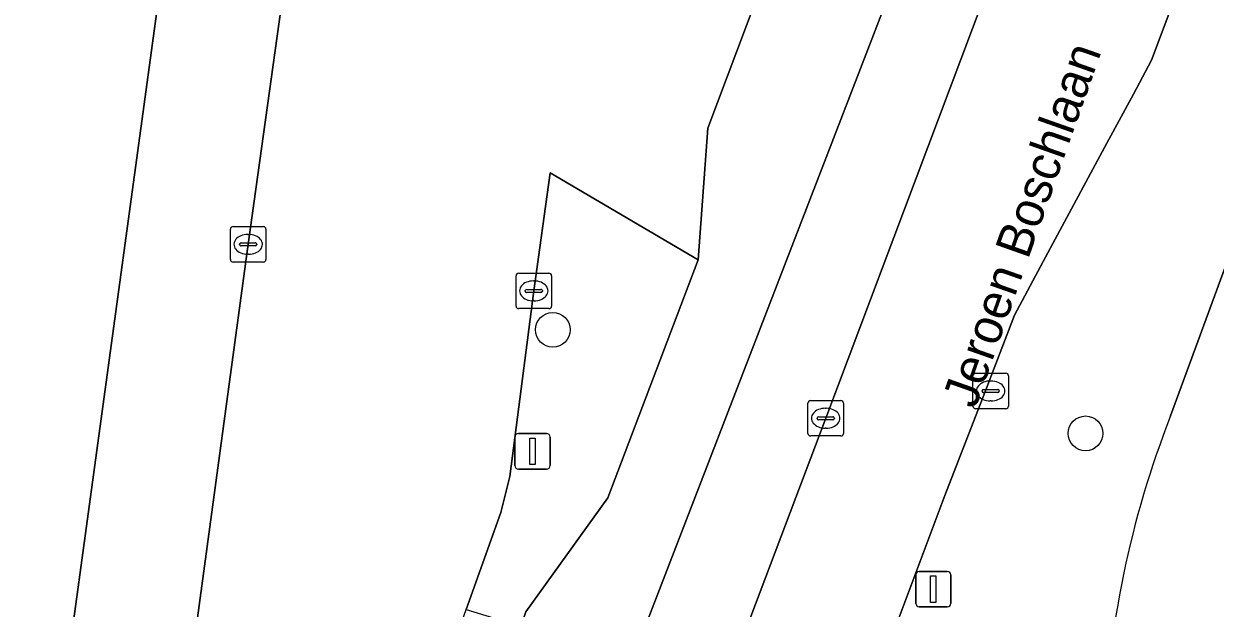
# Model space of a CAD drawing. Extents: x 162172 to 163187, y 382874 to 383685.
# Drawn here: x 163098.41 to 163131.97, y 383004.01 to 383020.47 of the extents above; entities that cross this region are included whole.
import ezdxf

# ---------------------------------------------------------------- set-up
doc = ezdxf.new("R2010")
doc.units = 0
for name, color, linetype in [('IMGEO_Berm_groen', 7, 'Continuous'), ('IMGEO_Boom', 7, 'Continuous'), ('IMGEO_Erf', 7, 'Continuous'), ('IMGEO_Fietspad_gesloten', 7, 'Continuous'), ('IMGEO_Kolk', 7, 'Continuous'), ('IMGEO_Lichtmast', 7, 'Continuous'), ('IMGEO_Openbare_ruimte_label', 7, 'Continuous'), ('IMGEO_Parkeervlak_open', 7, 'Continuous'), ('IMGEO_Rijbaan_lokaal_gesloten', 7, 'Continuous'), ('IMGEO_Voetpad_open', 7, 'Continuous')]:
    doc.layers.add(name, color=color, linetype=linetype)

msp = doc.modelspace()

# ---------------------------------------------------------------- linework, layer by layer
at = {"layer": 'IMGEO_Berm_groen'}
for points in [[(163142.501, 383044.918), (163137.777, 383032.423), (163135.415, 383033.359), (163134.125, 383029.959), (163130.174, 383019.451), (163129.662, 383018.485), (163128.915, 383017.105), (163127.523, 383014.531), (163127.123, 383013.779), (163126.316, 383012.264), (163125.474, 383010.089), (163124.351, 383007.183), (163121.897, 383000.656), (163120.735, 382997.497), (163120.127, 382995.283), (163117.88, 382989.013)], [(163130.709, 383009.426), (163138.112, 383029.587)], [(163138.112, 383029.587), (163130.709, 383009.426)]]:
    msp.add_lwpolyline(points, dxfattribs=at)
msp.add_lwpolyline([(163117.406, 383013.827), (163113.236, 383016.27), (163112.775, 383012.95), (163112.099, 383007.718), (163111.846, 383006.708), (163110.871, 383003.977), (163112.409, 383003.508), (163112.554, 383003.909), (163114.863, 383007.118)], close=True, dxfattribs=at)
msp.add_arc((163156.244, 382999.418), 27.426, 158.5987, 178.0992, dxfattribs=at)
msp.add_arc((163156.244, 382999.418), 27.426, 158.5987, 178.0992, dxfattribs=at)
at = {"layer": 'IMGEO_Boom'}
for centre in [(163113.311, 383011.854), (163128.316, 383008.936)]:
    msp.add_circle(centre, 0.489, dxfattribs=at)
at = {"layer": 'IMGEO_Erf'}
msp.add_lwpolyline([(163098.172, 383039.026), (163098.631, 383038.933), (163096.551, 383029.516), (163093.637, 383030.155), (163092.186, 383030.473), (163088.911, 383015.365), (163090.381, 383015.036), (163095.779, 383013.826), (163092.68, 383000), (163090.912, 382992.113), (163093.008, 382991.643), (163092.948, 382991.201), (163097.992, 382990.342), (163099.312, 383000), (163102.12, 383020.545), (163105.322, 383043.799)], dxfattribs=at)
at = {"layer": 'IMGEO_Fietspad_gesloten'}
for points in [[(163126.175, 383040.302), (163125.052, 383037.224), (163120.155, 383024.119), (163117.673, 383017.534), (163117.406, 383013.827), (163114.863, 383007.118), (163112.554, 383003.909), (163112.409, 383003.508), (163111.139, 383000), (163108.118, 382991.652), (163106.398, 382986.646)], [(163115.606, 383002.688), (163123.356, 383022.795)]]:
    msp.add_lwpolyline(points, dxfattribs=at)
at = {"layer": 'IMGEO_Kolk'}
for p, q in [((163104.232, 383013.834), (163104.232, 383014.686)), ((163104.307, 383014.76), (163105.159, 383014.76)), ((163105.233, 383014.686), (163105.233, 383013.834)), ((163104.72, 383014.54), (163104.745, 383014.54)), ((163104.491, 383014.254), (163104.491, 383014.266)), ((163104.929, 383014.217), (163104.531, 383014.217)), ((163104.534, 383014.303), (163104.932, 383014.303)), ((163104.743, 383013.98), (163104.718, 383013.98)), ((163104.975, 383014.266), (163104.975, 383014.254)), ((163105.159, 383013.76), (163104.307, 383013.76)), ((163112.275, 383012.523), (163112.275, 383013.375)), ((163112.35, 383013.449), (163113.202, 383013.449)), ((163113.276, 383013.375), (163113.276, 383012.523)), ((163112.577, 383012.992), (163112.975, 383012.992)), ((163112.763, 383013.229), (163112.788, 383013.229)), ((163112.534, 383012.943), (163112.534, 383012.955)), ((163112.972, 383012.906), (163112.574, 383012.906)), ((163112.786, 383012.669), (163112.761, 383012.669)), ((163113.018, 383012.955), (163113.018, 383012.943)), ((163113.202, 383012.449), (163112.35, 383012.449)), ((163125.218, 383010.631), (163126.07, 383010.631)), ((163125.143, 383009.705), (163125.143, 383010.557)), ((163125.631, 383010.411), (163125.656, 383010.411)), ((163126.144, 383010.557), (163126.144, 383009.705)), ((163125.402, 383010.125), (163125.402, 383010.137)), ((163125.84, 383010.088), (163125.442, 383010.088)), ((163125.445, 383010.174), (163125.843, 383010.174)), ((163125.886, 383010.137), (163125.886, 383010.125)), ((163120.497, 383008.936), (163120.497, 383009.788)), ((163120.572, 383009.862), (163121.424, 383009.862)), ((163120.985, 383009.642), (163121.01, 383009.642)), ((163121.498, 383009.788), (163121.498, 383008.936)), ((163126.07, 383009.631), (163125.218, 383009.631)), ((163125.654, 383009.851), (163125.629, 383009.851)), ((163120.756, 383009.356), (163120.756, 383009.368)), ((163121.194, 383009.319), (163120.796, 383009.319)), ((163120.799, 383009.405), (163121.197, 383009.405)), ((163121.24, 383009.368), (163121.24, 383009.356)), ((163121.008, 383009.082), (163120.983, 383009.082)), ((163121.424, 383008.862), (163120.572, 383008.862))]:
    msp.add_line(p, q, dxfattribs=at)
for points in [[(163104.232, 383013.834), (163104.232, 383014.686)], [(163104.307, 383014.76), (163105.159, 383014.76)], [(163105.233, 383014.686), (163105.233, 383013.834)], [(163105.159, 383013.76), (163104.307, 383013.76)], [(163112.275, 383012.523), (163112.275, 383013.375)], [(163112.35, 383013.449), (163113.202, 383013.449)], [(163113.276, 383013.375), (163113.276, 383012.523)], [(163113.202, 383012.449), (163112.35, 383012.449)], [(163125.218, 383010.631), (163126.07, 383010.631)], [(163125.143, 383009.705), (163125.143, 383010.557)], [(163126.144, 383010.557), (163126.144, 383009.705)], [(163120.497, 383008.936), (163120.497, 383009.788)], [(163120.572, 383009.862), (163121.424, 383009.862)], [(163121.498, 383009.788), (163121.498, 383008.936)], [(163126.07, 383009.631), (163125.218, 383009.631)], [(163121.424, 383008.862), (163120.572, 383008.862)]]:
    msp.add_lwpolyline(points, dxfattribs=at)
for centre, radius, start, end in [((163104.309, 383014.684), 0.0765, 91.552, 178.448), ((163104.309, 383014.684), 0.0765, 91.552, 178.448), ((163105.157, 383014.684), 0.0765, 1.552, 88.448), ((163105.157, 383014.684), 0.0765, 1.552, 88.448), ((163104.531, 383014.263), 0.0403, 85.8775, 175.7526), ((163104.528, 383014.253), 0.0366, 178.938, 274.7102), ((163104.932, 383014.26), 0.043, 264.8664, 352.4533), ((163104.936, 383014.265), 0.0386, 1.7309, 96.639), ((163104.309, 383013.836), 0.0765, 181.552, 268.448), ((163104.309, 383013.836), 0.0765, 181.552, 268.448), ((163105.157, 383013.836), 0.0765, 271.552, 358.448), ((163105.157, 383013.836), 0.0765, 271.552, 358.448), ((163112.352, 383013.373), 0.0765, 91.552, 178.448), ((163112.352, 383013.373), 0.0765, 91.552, 178.448), ((163113.2, 383013.373), 0.0765, 1.552, 88.448), ((163113.2, 383013.373), 0.0765, 1.552, 88.448), ((163112.574, 383012.952), 0.0403, 85.8775, 175.7526), ((163112.979, 383012.954), 0.0386, 1.7309, 96.639), ((163112.571, 383012.942), 0.0366, 178.938, 274.7102), ((163112.975, 383012.949), 0.043, 264.8664, 352.4533), ((163112.352, 383012.525), 0.0765, 181.552, 268.448), ((163112.352, 383012.525), 0.0765, 181.552, 268.448), ((163113.2, 383012.525), 0.0765, 271.552, 358.448), ((163113.2, 383012.525), 0.0765, 271.552, 358.448), ((163125.22, 383010.555), 0.0765, 91.552, 178.448), ((163125.22, 383010.555), 0.0765, 91.552, 178.448), ((163126.068, 383010.555), 0.0765, 1.552, 88.448), ((163126.068, 383010.555), 0.0765, 1.552, 88.448), ((163125.442, 383010.134), 0.0403, 85.8775, 175.7526), ((163125.439, 383010.124), 0.0366, 178.938, 274.7102), ((163125.843, 383010.131), 0.043, 264.8664, 352.4533), ((163125.847, 383010.136), 0.0386, 1.7309, 96.639), ((163120.574, 383009.786), 0.0765, 91.552, 178.448), ((163120.574, 383009.786), 0.0765, 91.552, 178.448), ((163121.422, 383009.786), 0.0765, 1.552, 88.448), ((163121.422, 383009.786), 0.0765, 1.552, 88.448), ((163125.22, 383009.707), 0.0765, 181.552, 268.448), ((163125.22, 383009.707), 0.0765, 181.552, 268.448), ((163126.068, 383009.707), 0.0765, 271.552, 358.448), ((163126.068, 383009.707), 0.0765, 271.552, 358.448), ((163120.796, 383009.365), 0.0403, 85.8775, 175.7526), ((163120.793, 383009.355), 0.0366, 178.938, 274.7102), ((163121.197, 383009.362), 0.043, 264.8664, 352.4533), ((163121.201, 383009.367), 0.0386, 1.7309, 96.639), ((163120.574, 383008.938), 0.0765, 181.552, 268.448), ((163120.574, 383008.938), 0.0765, 181.552, 268.448), ((163121.422, 383008.938), 0.0765, 271.552, 358.448), ((163121.422, 383008.938), 0.0765, 271.552, 358.448)]:
    msp.add_arc(centre, radius, start, end, dxfattribs=at)
for centre, major_axis, ratio, start_param, end_param in [((163104.719, 383014.26), (-0.387, 0.002), 0.722429, 4.712389, 7.853982), ((163104.744, 383014.26), (-0.39, 0.002), 0.717154, 1.570796, 4.712389), ((163112.762, 383012.949), (-0.387, 0.002), 0.722429, 4.712389, 7.853982), ((163112.787, 383012.949), (-0.39, 0.002), 0.717154, 1.570796, 4.712389), ((163125.63, 383010.131), (-0.387, 0.002), 0.722429, 4.712389, 7.853982), ((163125.655, 383010.131), (-0.39, 0.002), 0.717154, 1.570796, 4.712389), ((163120.984, 383009.362), (-0.387, 0.002), 0.722429, 4.712389, 7.853982), ((163121.009, 383009.362), (-0.39, 0.002), 0.717154, 1.570796, 4.712389)]:
    msp.add_ellipse(centre, major_axis=major_axis, ratio=ratio, start_param=start_param, end_param=end_param, dxfattribs=at)
at = {"layer": 'IMGEO_Lichtmast'}
for p, q in [((163112.245, 383008.03), (163112.245, 383008.83)), ((163112.245, 383008.83), (163112.245, 383008.03)), ((163112.345, 383008.93), (163113.135, 383008.93)), ((163113.135, 383008.93), (163112.345, 383008.93)), ((163113.235, 383008.83), (163113.235, 383008.03)), ((163113.235, 383008.03), (163113.235, 383008.83)), ((163113.135, 383007.93), (163112.345, 383007.93)), ((163112.345, 383007.93), (163113.135, 383007.93)), ((163123.532, 383004.147), (163123.532, 383004.947)), ((163123.532, 383004.947), (163123.532, 383004.147)), ((163123.632, 383005.047), (163124.422, 383005.047)), ((163124.422, 383005.047), (163123.632, 383005.047)), ((163124.522, 383004.947), (163124.522, 383004.147)), ((163124.522, 383004.147), (163124.522, 383004.947)), ((163124.422, 383004.047), (163123.632, 383004.047)), ((163123.632, 383004.047), (163124.422, 383004.047))]:
    msp.add_line(p, q, dxfattribs=at)
for points in [[(163112.665, 383008.805), (163112.815, 383008.805), (163112.815, 383008.055), (163112.665, 383008.055), (163112.665, 383008.805)], [(163123.952, 383004.922), (163124.102, 383004.922), (163124.102, 383004.172), (163123.952, 383004.172), (163123.952, 383004.922)]]:
    msp.add_lwpolyline(points, dxfattribs=at)
for centre, start, end in [((163112.345, 383008.83), 90, 180), ((163112.345, 383008.83), 90, 180), ((163113.135, 383008.83), 0, 90), ((163113.135, 383008.83), 360, 90), ((163112.345, 383008.03), 180, 270), ((163112.345, 383008.03), 180, 270), ((163113.135, 383008.03), 270, 0), ((163113.135, 383008.03), 270, 0), ((163123.632, 383004.947), 90, 180), ((163123.632, 383004.947), 90, 180), ((163124.422, 383004.947), 0, 90), ((163124.422, 383004.947), 360, 90), ((163123.632, 383004.147), 180, 270), ((163123.632, 383004.147), 180, 270), ((163124.422, 383004.147), 270, 0), ((163124.422, 383004.147), 270, 0)]:
    msp.add_arc(centre, 0.1, start, end, dxfattribs=at)
at = {"layer": 'IMGEO_Parkeervlak_open'}
msp.add_lwpolyline([(163111.846, 383006.708), (163112.099, 383007.718), (163112.775, 383012.95), (163113.236, 383016.27), (163117.406, 383013.827), (163117.673, 383017.534), (163120.155, 383024.119), (163114.374, 383024.162), (163116.626, 383040.467), (163108.479, 383041.665), (163108.374, 383040.4), (163104.732, 383014.26), (163102.802, 383000), (163101.432, 382989.882), (163105.315, 382988.417), (163109.451, 383000), (163110.871, 383003.977)], close=True, dxfattribs=at)
for points in [[(163117.462, 383000), (163121, 383009.363), (163129.262, 383031.324), (163130.477, 383034.481), (163129.911, 383034.058), (163127.4, 383032.792)], [(163126.868, 383032.181), (163123.356, 383022.795), (163115.606, 383002.688), (163115.196, 383001.603), (163114.314, 382999.125), (163110.841, 382989.408)]]:
    msp.add_lwpolyline(points, dxfattribs=at)
at = {"layer": 'IMGEO_Rijbaan_lokaal_gesloten'}
for points in [[(163117.88, 382989.013), (163120.127, 382995.283), (163120.735, 382997.497), (163121.897, 383000.656), (163124.351, 383007.183), (163125.474, 383010.089), (163126.316, 383012.264), (163127.123, 383013.779), (163127.523, 383014.531), (163128.915, 383017.105), (163129.662, 383018.485), (163130.174, 383019.451), (163134.125, 383029.959), (163135.415, 383033.359), (163140.16, 383045.987), (163129.144, 383045.377)], [(163130.477, 383034.481), (163129.262, 383031.324), (163121, 383009.363), (163117.462, 383000)]]:
    msp.add_lwpolyline(points, dxfattribs=at)
at = {"layer": 'IMGEO_Voetpad_open'}
msp.add_lwpolyline([(163105.322, 383043.799), (163102.12, 383020.545), (163099.312, 383000), (163097.992, 382990.342), (163097.909, 382989.737), (163101.209, 382989.271), (163101.285, 382989.906), (163101.432, 382989.882), (163102.802, 383000), (163104.732, 383014.26), (163108.374, 383040.4), (163108.479, 383041.665), (163108.365, 383041.696), (163108.684, 383043.824)], dxfattribs=at)

# ---------------------------------------------------------------- texts
at = {"layer": 'IMGEO_Openbare_ruimte_label'}
msp.add_text('Jeroen Boschlaan', height=1, rotation=70.5504, dxfattribs=at).set_placement((163125.207, 383009.604))

doc.saveas('drawing.dxf')
